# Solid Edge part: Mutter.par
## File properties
Sűrűség: 0,000 kg/m^3
Pontosság: 0,990
Author: bmolnar
Last saved by: psaghy
Revision: 77
Username: bmolnar
Dokumentum tartalom típus: 0
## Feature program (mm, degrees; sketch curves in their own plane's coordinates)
base feature "unnamed BaseFeature 1"
sketch for "Furat_1" plane through (8, 0, 0) normal (1, 0, 0) x-axis (0, 0, 1)
hole "Furat_1" through  StartChamferOffset = 0.49 mm; StartChamferAngle = 45 deg
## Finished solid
Body 1: solid body, 23 faces, 47 edges, 26 vertices.
  Faces by surface: cone 14, plane 8, cylinder 1
  Edges by curve: spline 24, circle 16, line 7
Bounding box of the edges (mm): 8.000 x 27.713 x 24.000, from (0, -13.8564, -12) to (8, 13.8564, 12).
Cylindrical faces by radius (mm): R7.188 x1
Conical faces (half-angle, radius in mm at the cone's reference point): 45 deg R7.678 x1, 60 deg R7.5939 x1, 60 deg R12.9282 x12
Planar faces by outward normal: +x 1, +z 1, -x 1, -z 1, oblique 4
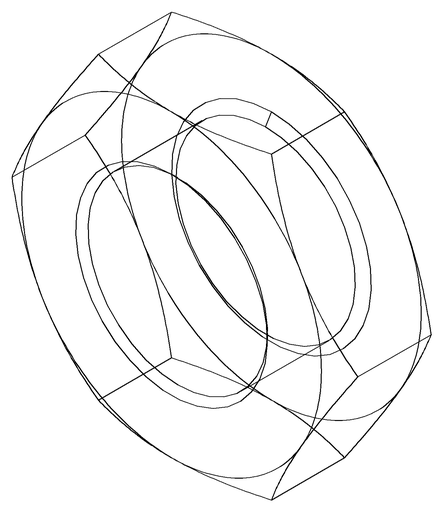
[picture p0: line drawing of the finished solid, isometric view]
